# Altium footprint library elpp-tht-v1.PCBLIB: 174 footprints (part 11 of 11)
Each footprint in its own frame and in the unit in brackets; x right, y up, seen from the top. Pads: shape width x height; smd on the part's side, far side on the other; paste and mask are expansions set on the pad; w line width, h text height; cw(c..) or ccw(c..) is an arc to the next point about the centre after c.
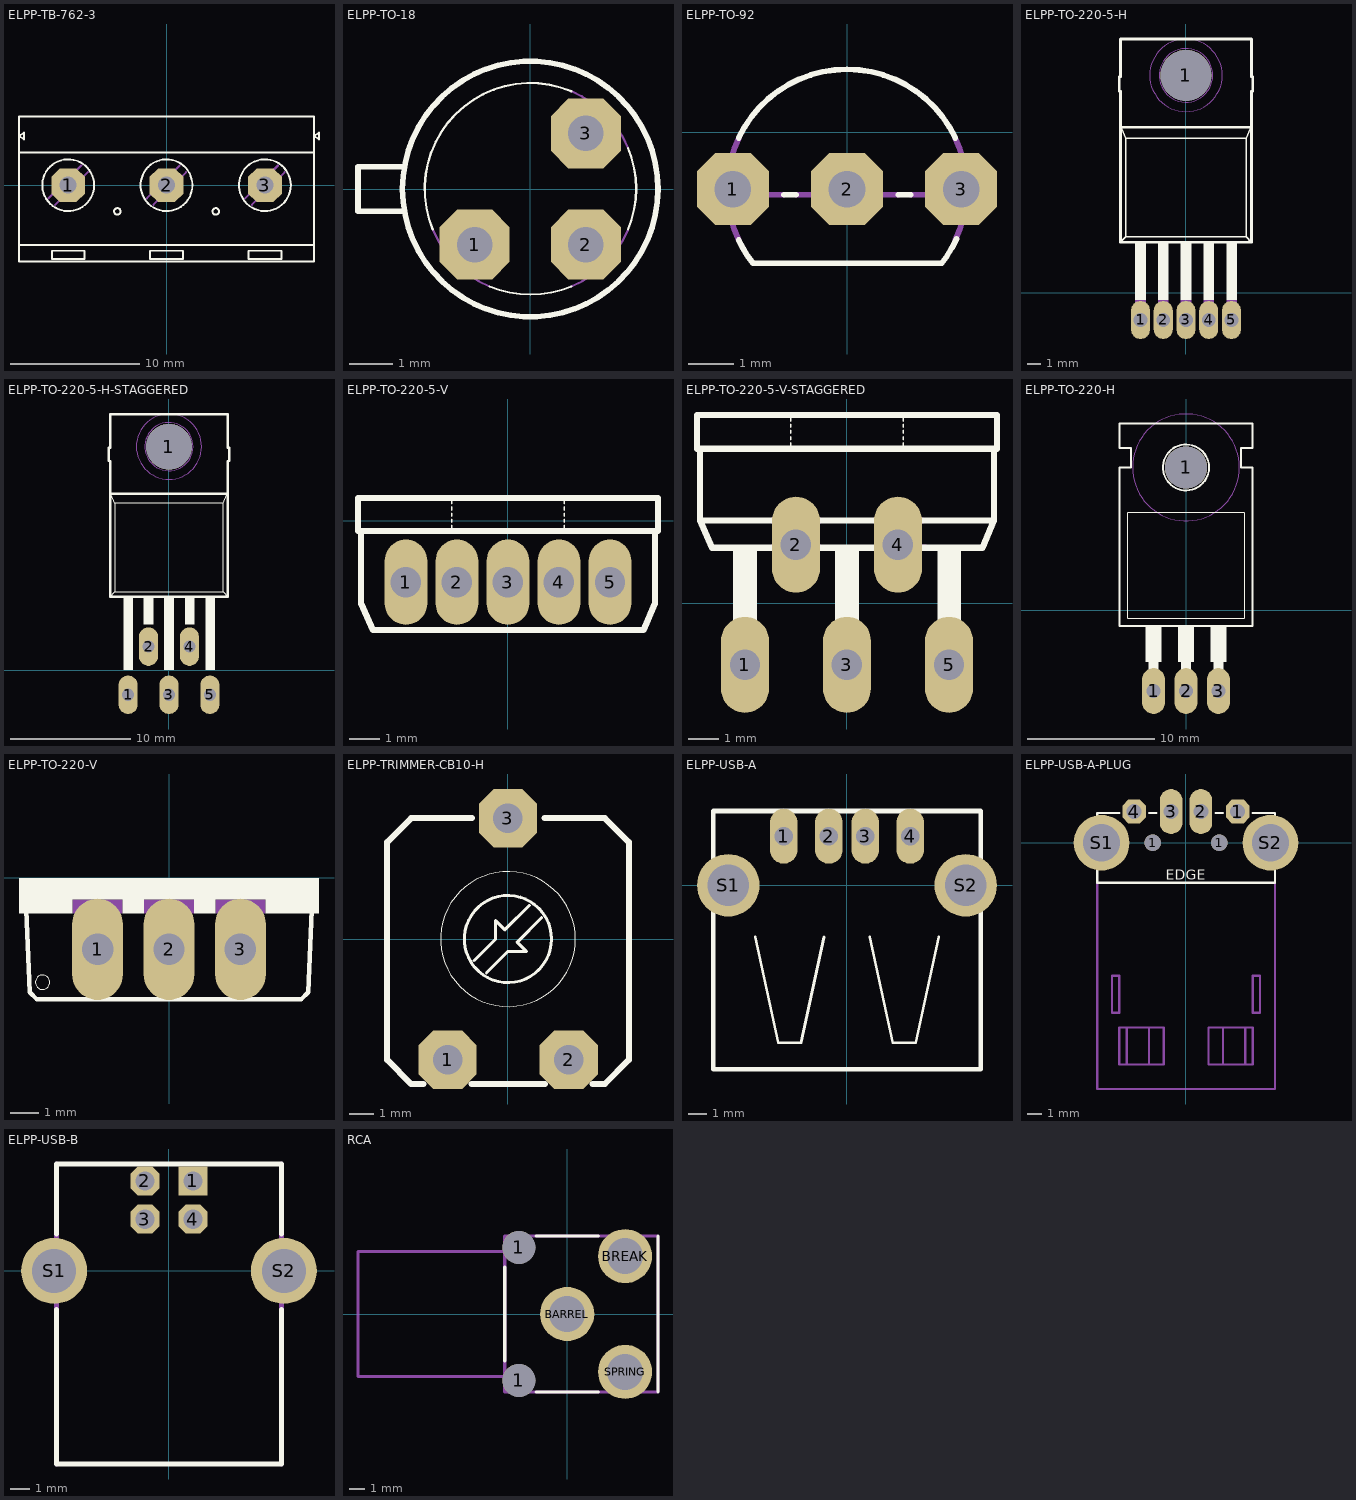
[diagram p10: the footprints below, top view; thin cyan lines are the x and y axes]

## ELPP-TB-762-3 [mil]
pads (3):
  oct 103x103 hole 52: 1(-300,0) 2(0,0) 3(300,0)
Top Overlay:
  circle w6: c-300,0 r79
  circle w6: c0,0 r79
  circle w6: c300,0 r79
  circle w6: c-150,-80 r10
  circle w6: c150,-80 r10
  lines w6: -450,-182.28 -450,-232.28 450,-232.28 450,-182.28 ; -450,-182.28 -450,100 ; -450,-182.28 450,-182.28 ; -450,100 450,100 ; -450,100 -450,150 ; -450,150 -450,209 450,209 450,150 ; -450,150 -435,160 -435,140 -450,150 ; 450,-182.28 450,100 ; 450,100 450,150 ; 450,150 465,160 465,140 450,150 ; -350,-225 -350,-200 -250,-200 -250,-225 -350,-225 ; -50,-225 -50,-200 50,-200 50,-225 -50,-225 ; 250,-225 250,-200 350,-200 350,-225 250,-225
Mechanical 2:
  text ">NAME" at -450,250 h42.5
Mechanical 4:
  text ">VALUE" at -450,-300 h42.5
Mechanical 16:
  lines w6: -360,-40 -260,60 ; -340,-60 -240,40 ; -60,-40 40,60 ; -40,-60 60,40 ; 240,-40 340,60 ; 260,-60 360,40

## ELPP-TO-18 [mil]
pads (3):
  oct 63x63 hole 32: 1(-50,-50) 2(50,-50) 3(50,50)
Top Overlay:
  circle w5: c0,0 r115
  lines w2: -87.68,-36.57 cw(c0.28,0.07) 37,88 ; -36.57,-87.68 ccw(c0.21,0.51) 37,-87.68 ; 88,-36.57 ccw(c-0.19,0.21) 88,37
  lines w5: -113.25,-20 -155,-20 -155,20 -113.25,20
Mechanical 2:
  text ">NAME" at 125,0 h42.5
Mechanical 4:
  text ">VALUE" at 125,-75 h42.5
Mechanical 16:
  lines w2: -87.68,-36.57 ccw(c0,0) -36.57,-87.68 ; 37,-87.68 ccw(c0.38,-0.13) 88,-36.57 ; 37,88 cw(c0.51,0.51) 88,37
  text "1" at -75,-50 h77.5
  text "2" at 25,-50 h77.5
  text "3" at 0,25 h77.5

## ELPP-TO-92 [mil]
pads (3):
  oct 63x63 hole 32: 1(-100,-50) 2(0,-50) 3(100,-50)
Top Overlay:
  lines w5: -95.02,-94.72 ccw(c-0.02,-50) -82.48,-115 83,-115 ccw(c0.55,-49.91) 96,-93.77 ; -95,-5.28 cw(c0,-50) 95,-5.28 ; -55.28,-55 -44.72,-55 ; 45,-55 56,-55
Mechanical 2:
  text ">NAME" at -100,70 h42.5
Mechanical 4:
  text ">VALUE" at -100,-180 h42.5
Mechanical 16:
  lines w5: -104.88,-55 -55.28,-55 ; -95,-94.72 cw(c0,-50) -95,-5.28 ; -44.72,-55 45,-55 ; 56,-55 105,-55 ; 95,-94.72 ccw(c0,-50) 95,-5.28

## ELPP-TO-220-5-H [mil]
pads (6):
  oval 56x112 hole 40: 1(-133.86,-80.71) 2(-66.93,-80.71) 3(0,-80.71) 4(67,-80.71) 5(134,-80.71)
  round 150 hole 150: 1(0,640)
Top Overlay:
  rectangle: -149.61,-21.65 -118.11,144
  rectangle: -15.75,-21.65 16,144
  rectangle: 119,-21.65 150,144
  rectangle: -82.68,-21.65 -51.18,144
  rectangle: 52,-21.65 83,144
  lines w4: -192.91,148 -177.17,164 ; -188.98,483 -177.17,455 ; 189,483 178,455 ; 193,148 178,164 ; -177.17,164 178,164 ; -177.17,164 -177.17,455 ; -177.17,455 178,455 ; 178,164 178,455
  lines w8: -196.85,593 -196.85,636 ; -192.91,593 -192.91,487 ; -192.91,636 -192.91,747 193,747 193,636 ; 193,593 193,487 ; 197,593 197,636 ; -192.91,487 -192.91,148 193,148 193,487 ; -192.91,487 193,487
Mechanical 2:
  text ">NAME" at -190.71,761 h42.5
Mechanical 4:
  text ">VALUE" at 230,-110 h42.5
Mechanical 8:
  circle w0: c0,640 r79
Mechanical 9:
  circle w0: c0,640 r79
Mechanical 10:
  circle w0: c0,640 r107
Mechanical 16:
  rectangle: -149.61,-88.58 -118.11,-21.65
  rectangle: -15.75,-88.58 16,-21.65
  rectangle: 119,-88.58 150,-21.65
  rectangle: -82.68,-88.58 -51.18,-21.65
  rectangle: 52,-88.58 83,-21.65

## ELPP-TO-220-5-H-STAGGERED [mil]
pads (6):
  oval 63x126 hole 40: 1(-133.86,-80.71) 2(-66.93,77) 3(0,-80.71) 4(67,77) 5(134,-80.71)
  round 150 hole 150: 1(0,732)
Top Overlay:
  rectangle: -149.61,0 -118.11,238
  rectangle: -15.75,0 16,238
  rectangle: 119,0 150,238
  rectangle: -82.68,150 -51.18,238
  rectangle: 52,150 83,238
  lines w4: -192.91,240 -177.17,256 ; -188.98,575 -177.17,547 ; 189,575 178,547 ; 193,240 178,256 ; -177.17,256 178,256 ; -177.17,256 -177.17,547 ; -177.17,547 178,547 ; 178,256 178,547
  lines w8: -196.85,685 -196.85,728 ; -192.91,685 -192.91,578 ; -192.91,728 -192.91,838 193,838 193,728 ; 193,685 193,578 ; 197,685 197,728 ; -192.91,578 -192.91,240 193,240 193,578 ; -192.91,578 193,578
Mechanical 2:
  text ">NAME" at -190.71,853 h42.5
Mechanical 4:
  text ">VALUE" at 230,-110 h42.5
Mechanical 8:
  circle w0: c0,732 r79
Mechanical 9:
  circle w0: c0,732 r79
Mechanical 10:
  circle w0: c0,732 r107

## ELPP-TO-220-5-V [mil]
pads (5):
  oval 56x112 hole 40: 1(-133.86,-80.71) 2(-66.93,-80.71) 3(0,-80.71) 4(67,-80.71) 5(134,-80.71)
Top Overlay:
  lines w2: -73.62,-12.6 -73.62,-5.91 ; -73.62,-1.97 -73.62,2 ; -73.62,6 -73.62,10 ; -73.62,14 -73.62,18 ; -73.62,22 -73.62,26 ; 74,-12.6 74,-5.91 ; 74,-1.97 74,2 ; 74,6 74,10 ; 74,14 74,18 ; 74,22 74,26
  lines w8: -192.91,-13.78 -192.91,-108.27 -177.17,-143.7 178,-143.7 193,-108.27 193,-13.78 ; -196.85,-13.78 -196.85,30 197,30 197,-13.78 -196.85,-13.78
Mechanical 2:
  text ">NAME" at -200,64 h42.5
Mechanical 4:
  text ">VALUE" at 250,-100 h42.5

## ELPP-TO-220-5-V-STAGGERED [mil]
pads (5):
  oval 63x126 hole 40: 1(-133.86,-80.71) 2(-66.93,77) 3(0,-80.71) 4(67,77) 5(134,-80.71)
Top Overlay:
  rectangle: -149.61,-21.65 -118.11,69
  rectangle: -15.75,-21.65 16,69
  rectangle: 119,-21.65 150,69
  lines w2: -73.62,204 -73.62,211 ; -73.62,215 -73.62,219 ; -73.62,223 -73.62,227 ; -73.62,231 -73.62,235 ; -73.62,239 -73.62,243 ; 74,204 74,211 ; 74,215 74,219 ; 74,223 74,227 ; 74,231 74,235 ; 74,239 74,243
  lines w8: -192.91,203 -192.91,109 ; -98.43,73 -177.17,73 -192.91,109 ; -98.43,109 -192.91,109 ; -35.43,73 36,73 ; -35.43,109 36,109 ; 99,73 178,73 193,109 ; 99,109 193,109 ; 193,203 193,109 ; -196.85,203 -196.85,247 197,247 197,203 -196.85,203
Mechanical 2:
  text ">NAME" at -200,280 h42.5
Mechanical 4:
  text ">VALUE" at 250,-100 h42.5
Mechanical 16:
  rectangle: -149.61,-80.71 -118.11,-21.65
  rectangle: -15.75,-80.71 16,-21.65
  rectangle: 119,-80.71 150,-21.65
  lines w8: -98.43,73 -35.43,73 ; -98.43,109 -35.43,109 ; 36,109 99,109 ; 40,73 103,73

## ELPP-TO-220-H [mil]
pads (4):
  oval 71x142 hole 44: 1(-100,-250) 2(0,-250) 3(100,-250)
  round 130 hole 130: 1(0,440)
Top Overlay:
  circle w6: c0,440 r71
  rectangle: 85,-185 115,-160
  rectangle: -15,-185 15,-160
  rectangle: -115,-185 -85,-160
  rectangle: -125,-160 -75,-50
  rectangle: -25,-160 25,-50
  rectangle: 75,-160 125,-50
  lines w2: -180,-25 180,-25 180,300 -180,300 -180,-25
  lines w6: -205,-50 205,-50 205,440 170,440 170,500 205,500 205,575 -205,575 -205,500 -170,500 -170,440 -205,440 -205,-50
Mechanical 2:
  text ">NAME" at -150,605 h42.5
Mechanical 4:
  text ">VALUE" at -155,100 h42.5
Mechanical 9:
  circle w0: c0,440 r165
Mechanical 10:
  circle w0: c0,440 r165
Mechanical 16:
  rectangle: -115,-260 -85,-185
  rectangle: -15,-260 15,-185
  rectangle: 85,-260 115,-185

## ELPP-TO-220-V [mil]
pads (3):
  oval 71x142 hole 44: 1(-100,-100) 2(0,-100) 3(100,-100)
Top Overlay:
  circle w0: c-177,-146 r10
  rectangle: -210,-30 210,0
  rectangle: -210,-50 -135,-30
  rectangle: -65,-50 -35,-30
  rectangle: 35,-50 65,-30
  rectangle: 135,-50 210,-30
  lines w6: -200,-45 -195,-160 -185,-170 185,-170 195,-160 200,-45
Mechanical 2:
  text ">NAME" at -200,-238 h42.5
Mechanical 4:
  text ">VALUE" at -200,-300 h42.5
Mechanical 16:
  rectangle: -135,-50 -65,-30
  rectangle: -35,-50 35,-30
  rectangle: 65,-50 135,-30

## ELPP-TRIMMER-CB10-H [mil]
pads (3):
  oct 95x95 hole 48: 1(-98.43,-196.85) 2(99,-196.85) 3(0,197)
Top Overlay:
  circle w5: c0,0 r71
  circle w2: c0,0 r110
  lines w5: -55,-35 -20,0 -20,30 -5,15 35,55 ; -35,-55 0,-20 30,-20 15,-5 55,35
  lines w10: -137.8,-236.22 -157.48,-236.22 -196.85,-196.85 -196.85,158 -157.48,197 -59.06,197 ; -59.06,-236.22 60,-236.22 ; 60,197 158,197 197,158 197,-196.85 158,-236.22 138,-236.22
Mechanical 2:
  text ">NAME" at -125,250 h42.5
Mechanical 4:
  text ">VALUE" at -120,-300 h42.5

## ELPP-USB-A [mil]
pads (6):
  oval 60x120 hole 40: 1(-137.8,107) 2(-39.37,107) 3(40,107) 4(138,107)
  round 136.5 hole 91: S1(-258.66,0) S2(259,0)
Top Overlay:
  lines w6: -200,-112.99 -150,-343.31 -100,-343.31 -50,-112.99 ; 50,-112.99 100,-343.31 150,-343.31 200,-112.99
  lines w10: -291.34,-401.18 292,-401.18 292,162 -291.34,162 -291.34,-401.18
Mechanical 2:
  text ">NAME" at -300,200 h42.5
Mechanical 4:
  text ">VALUE" at 360,-400 h42.5

## ELPP-USB-A-PLUG [mil]
pads (8):
  round 44 hole 44: 1(-88.58,0) 1(89,0)
  oct 63x63 hole 40: 1(138,83) 4(-137.8,83)
  oval 60x120 hole 40: 2(40,83) 3(-39.37,83)
  round 148.5 hole 99: S1(-224.41,0) S2(225,0)
Top Overlay:
  lines w6: -236.22,-59.06 -236.22,-106.3 237,-106.3 237,-59.06 ; -236.22,60 -236.22,79 -177.17,79 ; -98.43,79 -78.74,79 ; 79,79 99,79 ; 178,79 237,79 237,60
  text "EDGE" at -53.15,-98.43 h27.2
Mechanical 2:
  text ">NAME" at 212,102 h42.5
Mechanical 4:
  text ">VALUE" at 145,-151.81 h42.5
Mechanical 16:
  lines w6: -236.22,-106.3 -236.22,-655.51 237,-655.51 237,-106.3 ; -157.48,-590.55 -177.17,-590.55 -177.17,-492.13 -157.48,-492.13 ; -157.48,-590.55 -98.43,-590.55 ; -157.48,-590.55 -157.48,-492.13 ; -157.48,-492.13 -98.43,-492.13 ; -98.43,-590.55 -59.06,-590.55 -59.06,-492.13 -98.43,-492.13 ; -98.43,-590.55 -98.43,-492.13 ; 99,-590.55 60,-590.55 60,-492.13 99,-492.13 ; 99,-590.55 158,-590.55 ; 99,-590.55 99,-492.13 ; 99,-492.13 158,-492.13 ; 158,-590.55 178,-590.55 178,-492.13 158,-492.13 ; 158,-590.55 158,-570.87 158,-492.13 ; -196.85,-452.76 -196.85,-354.33 -177.17,-354.33 -177.17,-452.76 -196.85,-452.76 ; 178,-452.76 178,-354.33 197,-354.33 197,-452.76 178,-452.76

## ELPP-USB-B [mil]
pads (6):
  rect 60x60 hole 40: 1(50,186)
  oct 60x60 hole 40: 2(-49.21,186) 3(-49.21,107) 4(50,107)
  round 136.5 hole 91: S1(-237.01,0) S2(238,0)
Top Overlay:
  lines w10: -232.28,-79.53 -232.28,-399.61 233,-399.61 233,-79.53 ; -232.28,76 -232.28,221 233,221 233,76
Mechanical 2:
  text ">NAME" at -250,250 h42.5
Mechanical 4:
  text ">VALUE" at 300,-350 h42.5
Mechanical 16:
  lines w10: -232.28,-399.61 -232.28,221 ; 233,-399.61 233,221

## RCA [mil]
pads (5):
  round 83 hole 83: 1(-122.05,-167.32) 1(-122.05,168)
  round 136.5 hole 91: BARREL(0,0) BREAK(146,146) SPRING(146,-145.67)
Top Overlay:
  lines w8: -157.48,-118.11 -157.48,119 ; -78.74,-196.85 79,-196.85 ; -78.74,197 79,197 ; 229,-196.85 229,197
Mechanical 16:
  lines w8: -157.48,-157.48 -527.56,-157.48 -527.56,158 -157.48,158 ; -157.48,-196.85 -157.48,197 229,197 229,-196.85 -157.48,-196.85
